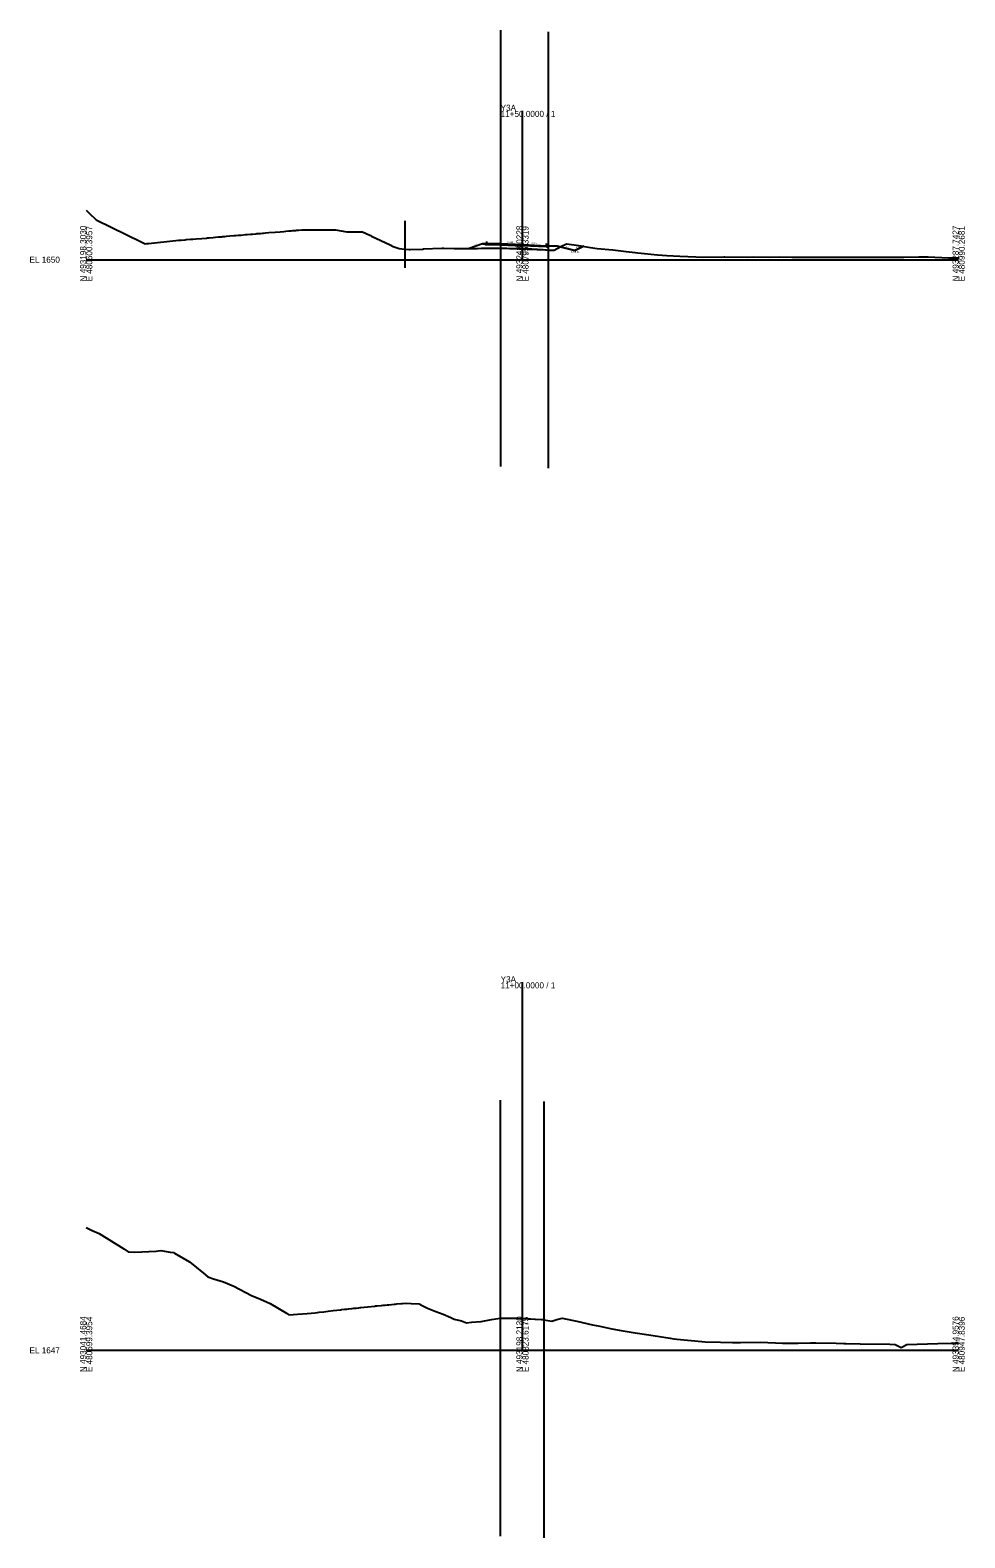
# Model space of a CAD drawing. Extents: x -26 to 403, y -10 to 3108.
# Drawn here: x -26 to 403, y 914 to 1605 of the extents above; entities that cross this region are included whole.
import ezdxf

# ---------------------------------------------------------------- set-up
doc = ezdxf.new("R2010")
doc.units = 0
for name, color, linetype in [('Exist Cross Section Cell', 7, 'Continuous'), ('Exist XS Center Line Elevation Label', 7, 'Continuous'), ('Exist XS Ground Line', 7, 'Continuous'), ('Prop Road Sect_ Boring - Header (ID Tx)', 7, 'Continuous'), ('Prop Road Sect_ Material - Tx (Composite Desc)', 7, 'Continuous'), ('Prop XS Ditch Slope Text', 7, 'Continuous'), ('Prop XS Ditch Standard Text', 7, 'Continuous'), ('Prop XS Dump Level', 7, 'Continuous'), ('Prop XS Earthwork Shape', 7, 'Continuous'), ('Prop XS EOT Tick Mark', 7, 'Continuous'), ('Prop XS Finish Grade', 7, 'Continuous'), ('Prop XS Finish Grade Earthwork', 7, 'Continuous'), ('Prop XS Finish Grade Pavement', 7, 'Continuous'), ('Prop XS Pvmt Edge Slope', 7, 'Continuous'), ('Prop XS SE Text', 7, 'Continuous'), ('Prop XS Side Slope Text', 7, 'Continuous'), ('Prop XS Subgrade Earthwork', 7, 'Continuous'), ('Scratch_Level_1', 7, 'Continuous'), ('Scratch_Level_4', 7, 'Continuous'), ('Scratch_Level_5', 7, 'Continuous')]:
    doc.layers.add(name, color=color, linetype=linetype)

msp = doc.modelspace()

# ---------------------------------------------------------------- linework, layer by layer
at = {"layer": 'Exist Cross Section Cell'}
for p, q in [((200, 1500), (200, 1568.23)), ((0, 1500), (200, 1500)), ((200, 1500), (400, 1500)), ((200, 1000), (200, 1168.72)), ((0, 1000), (200, 1000)), ((200, 1000), (400, 1000))]:
    msp.add_line(p, q, dxfattribs=at)
at = {"layer": 'Exist XS Ground Line'}
for points in [[(0, 1522.74), (1.43, 1521.37), (4.59, 1518.32), (25.48, 1508.09), (27.08, 1507.31), (27.82, 1507.39), (28.57, 1507.47), (41.07, 1508.82), (42.35, 1508.92), (42.82, 1508.95), (43.58, 1509.01), (45.32, 1509.14), (45.91, 1509.19), (47.89, 1509.34), (48.89, 1509.42), (50.47, 1509.55), (53.05, 1509.76), (55.14, 1509.92), (55.6, 1509.96), (56.34, 1510.03), (58.17, 1510.18), (59.3, 1510.28), (60.73, 1510.42), (62.04, 1510.54), (62.49, 1510.59), (62.86, 1510.62), (63.5, 1510.68), (64.28, 1510.75), (65.87, 1510.88), (67.65, 1511.02), (68.43, 1511.09), (69.74, 1511.2), (70.98, 1511.3), (73.03, 1511.48), (73.56, 1511.52), (73.87, 1511.55), (75.3, 1511.68), (76.24, 1511.76), (77.82, 1511.9), (78.17, 1511.93), (78.68, 1511.97), (79.48, 1512.04), (79.93, 1512.07), (80.87, 1512.15), (81.24, 1512.19), (82.21, 1512.27), (83.81, 1512.4), (86.59, 1512.62), (88.93, 1512.81), (90.58, 1512.94), (91.5, 1513.03), (92.95, 1513.16), (94.05, 1513.26), (94.72, 1513.32), (95.97, 1513.43), (96.47, 1513.47), (96.77, 1513.5), (97.5, 1513.55), (98.82, 1513.66), (99.51, 1513.71), (101.35, 1513.75), (109.82, 1513.74), (111.95, 1513.74), (113.14, 1513.75), (113.61, 1513.75), (114.25, 1513.61), (119.5, 1512.75), (124.95, 1512.8), (126.66, 1512.78), (129.97, 1511.28), (130.38, 1511.07), (130.84, 1510.78), (139.3, 1506.87), (140.69, 1506.04), (143.47, 1505.11), (144.72, 1504.92), (148, 1504.69), (148.53, 1504.71), (154.33, 1504.81), (154.7, 1504.94), (163.04, 1505.26), (164.02, 1505.24), (168.72, 1505.2), (170.95, 1505.18), (172.84, 1505.18), (173.59, 1505.18), (174.05, 1505.18), (176.14, 1505.18), (178.25, 1505.2), (178.72, 1505.2), (179.47, 1505.2), (181.28, 1505.21), (182.86, 1505.21), (183.86, 1505.22), (184.49, 1505.23), (186.42, 1505.23), (187.31, 1505.23), (188.67, 1505.22), (189.07, 1505.22), (189.88, 1505.23), (190.9, 1505.22), (191.58, 1505.22), (192.85, 1505.21), (194.13, 1505.19), (196.18, 1505.16), (196.7, 1505.15), (198.42, 1505.12), (199.47, 1505.11), (200, 1505.1), (201.18, 1505.08), (201.49, 1505.07), (201.81, 1505.06), (202.81, 1505.02), (204.35, 1504.95), (206.13, 1504.86), (206.92, 1504.82), (209.53, 1504.63), (210.6, 1504.53), (211.76, 1504.41), (214.54, 1504.32), (217.65, 1505.98), (220.2, 1507.2), (223.67, 1506.85), (231.14, 1505.61), (234.21, 1505.18), (241.4, 1504.46), (247.6, 1503.74), (251.66, 1503.25), (252.87, 1503.19), (261.92, 1502.26), (266.19, 1501.98), (272.19, 1501.61), (279.5, 1501.33), (282.45, 1501.21), (292.34, 1501.26), (292.82, 1501.26), (302.97, 1501.23), (306.14, 1501.27), (313.23, 1501.17), (317.68, 1501.29), (323.49, 1501.18), (326.03, 1501.21), (333.76, 1501.18), (337.07, 1501.16), (344.02, 1501.15), (346.09, 1501.18), (354.28, 1501.09), (359.4, 1501.13), (364.54, 1501.19), (367.76, 1501.12), (374.8, 1501.21), (381.8, 1501.26), (385.06, 1501.25), (386.04, 1501.25), (395.33, 1500.79), (399.35, 1500.86), (400, 1500.91)], [(0, 1056.24), (2.75, 1054.88), (5.99, 1053.49), (17.24, 1046.49), (19.22, 1045.22), (19.66, 1045.2), (22.2, 1045.07), (32.07, 1045.52), (34.28, 1045.7), (38.5, 1045.07), (40, 1044.83), (40.46, 1044.62), (47.44, 1040.54), (53.78, 1035.45), (55.83, 1033.77), (58.39, 1032.85), (62.95, 1031.39), (67.69, 1029.49), (75.79, 1025.16), (79.94, 1023.38), (84.31, 1021.45), (91.82, 1017.11), (92.95, 1016.23), (96.84, 1016.57), (101.34, 1016.94), (104.95, 1017.25), (106.02, 1017.37), (106.75, 1017.46), (109, 1017.72), (109.94, 1017.83), (110.87, 1017.94), (113.16, 1018.2), (114.89, 1018.4), (116.39, 1018.57), (116.71, 1018.6), (117.1, 1018.65), (118.47, 1018.8), (119.57, 1018.93), (120.25, 1019.01), (121.66, 1019.16), (122, 1019.2), (122.73, 1019.27), (123.75, 1019.38), (125.07, 1019.52), (125.56, 1019.57), (125.94, 1019.61), (127.37, 1019.76), (129.15, 1019.95), (132.3, 1020.29), (132.69, 1020.33), (133.01, 1020.36), (133.37, 1020.4), (135.44, 1020.59), (136.19, 1020.66), (137.14, 1020.76), (138.02, 1020.84), (138.73, 1020.9), (141.19, 1021.13), (141.81, 1021.19), (142.46, 1021.26), (144.54, 1021.46), (145.08, 1021.51), (146.28, 1021.58), (149.01, 1021.44), (152.59, 1021.37), (154.09, 1020.51), (156.52, 1019.29), (160.23, 1017.85), (163.71, 1016.57), (167.16, 1015.11), (168.64, 1014.26), (172.06, 1013.49), (174.43, 1012.64), (176.68, 1012.86), (181.11, 1013.27), (185.89, 1014.17), (189.75, 1014.73), (190.2, 1014.73), (190.95, 1014.73), (192.95, 1014.73), (193.54, 1014.72), (195.01, 1014.7), (196.12, 1014.69), (197.54, 1014.67), (199.25, 1014.64), (200.12, 1014.61), (201.56, 1014.55), (202.48, 1014.51), (203.84, 1014.44), (205.67, 1014.35), (206.02, 1014.32), (208.8, 1014.14), (209.17, 1014.11), (209.89, 1014.03), (212.63, 1013.46), (213.53, 1013.32), (215.77, 1014.07), (218.19, 1014.75), (224.96, 1013.31), (232.07, 1011.72), (233.82, 1011.44), (235.53, 1011.06), (240.94, 1009.93), (245.23, 1009.03), (251.63, 1008.01), (258, 1007.11), (267.74, 1005.57), (269.42, 1005.33), (270.76, 1005.17), (282.3, 1004.09), (283.84, 1003.96), (290.78, 1003.78), (296.28, 1003.54), (299.94, 1003.58), (309.04, 1003.74), (316.05, 1003.51), (319.26, 1003.31), (321.81, 1003.33), (326.38, 1003.34), (332.15, 1003.47), (334.57, 1003.45), (343.8, 1003.21), (347.33, 1003.12), (347.74, 1003.11), (348.25, 1003.11), (354.86, 1003.01), (368.5, 1002.8), (370.96, 1002.7), (371.84, 1002.26), (373.62, 1001.23), (376.24, 1002.62), (390.46, 1003.2), (396.56, 1003.24), (397.58, 1003.23), (398.38, 1003.25), (400, 1003.27)]]:
    msp.add_lwpolyline(points, dxfattribs=at)
at = {"layer": 'Prop Road Sect_ Boring - Header (ID Tx)'}
for points in [[(183.73, 1507.34), (182.67, 1507.3), (183.18, 1506.79)], [(211.02, 1506.41), (212.11, 1506.36), (211.59, 1505.84)]]:
    msp.add_lwpolyline(points, close=True, dxfattribs=at)
at = {"layer": 'Prop Road Sect_ Material - Tx (Composite Desc)'}
for points in [[(175.51, 1505.18), (176.14, 1505.18), (178.25, 1505.2), (178.72, 1505.2), (179.47, 1505.2), (181.28, 1505.21), (182.86, 1505.21), (183.86, 1505.22), (184.49, 1505.23), (186.42, 1505.23), (187.31, 1505.23), (188.67, 1505.22), (189.07, 1505.22), (189.88, 1505.23), (190.9, 1505.22), (191.58, 1505.22), (192.85, 1505.21), (194.13, 1505.19), (196.18, 1505.16), (196.7, 1505.15), (198.42, 1505.12), (199.47, 1505.11), (200, 1505.1), (201.18, 1505.08), (201.49, 1505.07), (201.81, 1505.06), (202.81, 1505.02), (204.35, 1504.95), (206.13, 1504.86), (206.92, 1504.82), (209.53, 1504.63), (210.6, 1504.53), (211.76, 1504.41), (214.54, 1504.32), (217.38, 1505.84), (216.02, 1506.18), (212.11, 1506.36), (211.59, 1505.84), (211.02, 1505.87), (199.98, 1506.37), (189.88, 1506.84), (183.73, 1506.8), (183.18, 1506.79), (182.67, 1507.3), (181.73, 1507.26)], [(217.38, 1505.84), (217.65, 1505.98), (220.2, 1507.2), (223.67, 1506.85), (227.95, 1506.14), (224.02, 1504.18)]]:
    msp.add_lwpolyline(points, close=True, dxfattribs=at)
at = {"layer": 'Prop XS Earthwork Shape'}
for points in [[(175.51, 1505.18), (176.14, 1505.18), (178.25, 1505.2), (178.72, 1505.2), (179.47, 1505.2), (181.28, 1505.21), (182.86, 1505.21), (183.86, 1505.22), (184.49, 1505.23), (186.42, 1505.23), (187.31, 1505.23), (188.67, 1505.22), (189.07, 1505.22), (189.88, 1505.23), (190.9, 1505.22), (191.58, 1505.22), (192.85, 1505.21), (194.13, 1505.19), (196.18, 1505.16), (196.7, 1505.15), (198.42, 1505.12), (199.47, 1505.11), (200, 1505.1), (201.18, 1505.08), (201.49, 1505.07), (201.81, 1505.06), (202.81, 1505.02), (204.35, 1504.95), (206.13, 1504.86), (206.92, 1504.82), (209.53, 1504.63), (210.6, 1504.53), (211.76, 1504.41), (214.54, 1504.32), (217.38, 1505.84), (216.02, 1506.18), (212.11, 1506.36), (211.59, 1505.84), (211.02, 1505.87), (199.98, 1506.37), (189.88, 1506.84), (183.73, 1506.8), (183.18, 1506.79), (182.67, 1507.3), (181.73, 1507.26)], [(217.38, 1505.84), (217.65, 1505.98), (220.2, 1507.2), (223.67, 1506.85), (227.95, 1506.14), (224.02, 1504.18)]]:
    msp.add_lwpolyline(points, close=True, dxfattribs=at)
at = {"layer": 'Prop XS EOT Tick Mark'}
for p, q in [((183.73, 1507.34), (183.73, 1508.34)), ((211.02, 1506.41), (211.02, 1507.41))]:
    msp.add_line(p, q, dxfattribs=at)
at = {"layer": 'Prop XS Finish Grade'}
for p, q in [((183.73, 1507.34), (182.67, 1507.3)), ((211.02, 1506.41), (212.11, 1506.36))]:
    msp.add_line(p, q, dxfattribs=at)
at = {"layer": 'Prop XS Finish Grade Earthwork'}
for p, q in [((181.73, 1507.26), (175.51, 1505.18)), ((181.73, 1507.26), (182.67, 1507.3)), ((212.11, 1506.36), (216.02, 1506.18)), ((216.02, 1506.18), (224.02, 1504.18)), ((224.02, 1504.18), (227.95, 1506.14))]:
    msp.add_line(p, q, dxfattribs=at)
at = {"layer": 'Prop XS Finish Grade Pavement'}
for p, q in [((189.88, 1507.38), (183.73, 1507.34)), ((189.88, 1507.38), (200, 1506.91)), ((200, 1506.91), (211.02, 1506.41))]:
    msp.add_line(p, q, dxfattribs=at)
at = {"layer": 'Prop XS Pvmt Edge Slope'}
for p, q in [((183.73, 1507.34), (183.18, 1506.79)), ((211.02, 1506.41), (211.59, 1505.84))]:
    msp.add_line(p, q, dxfattribs=at)
at = {"layer": 'Prop XS Subgrade Earthwork'}
for p, q in [((182.67, 1507.3), (183.18, 1506.79)), ((189.88, 1506.84), (183.73, 1506.8)), ((189.88, 1506.84), (199.98, 1506.37)), ((183.73, 1506.8), (183.18, 1506.79)), ((211.02, 1505.87), (199.98, 1506.37)), ((211.02, 1505.87), (211.59, 1505.84)), ((212.11, 1506.36), (211.59, 1505.84))]:
    msp.add_line(p, q, dxfattribs=at)
at = {"layer": 'Scratch_Level_1'}
for p, q in [((189.88, 1605.23), (189.88, 1405.23)), ((211.76, 1604.41), (211.76, 1404.41)), ((189.75, 1114.73), (189.75, 914.73)), ((209.89, 1114.03), (209.89, 914.03))]:
    msp.add_line(p, q, dxfattribs=at)
at = {"layer": 'Scratch_Level_4'}
msp.add_line((189.88, 1505.23), (211.02, 1504.48), dxfattribs=at)
at = {"layer": 'Scratch_Level_5'}
msp.add_line((146.1, 1517.82), (146.1, 1496.2), dxfattribs=at)

# ---------------------------------------------------------------- texts
at = {"layer": 'Exist Cross Section Cell'}
for s, p in [('Y3A', (190, 1568.23)), ('11+50.0000 / 1', (190, 1565.43)), ('EL 1650', (-26, 1498.6)), ('Y3A', (190, 1168.72)), ('11+00.0000 / 1', (190, 1165.92)), ('EL 1647', (-26, 998.6))]:
    msp.add_text(s, height=2.8, dxfattribs=at).set_placement(p)
for s, p in [('N 493198.3030', (0, 1490)), ('E 480600.3957', (2.8, 1490)), ('N 493243.0228', (200, 1490)), ('E 480795.3319', (202.8, 1490)), ('N 493287.7427', (400, 1490)), ('E 480990.2681', (402.8, 1490)), ('N 493041.4684', (0, 990)), ('E 480699.3954', (2.8, 990)), ('N 493198.2130', (200, 990)), ('E 480823.6175', (202.8, 990)), ('N 493354.9576', (400, 990)), ('E 480947.8396', (402.8, 990))]:
    msp.add_text(s, height=2.8, rotation=90, dxfattribs=at).set_placement(p)
at = {"layer": 'Exist XS Center Line Elevation Label'}
for s, p in [('1655.10', (198.07, 1502.2)), ('1661.62', (198.1, 1011.72))]:
    msp.add_text(s, height=0.9, dxfattribs=at).set_placement(p)
at = {"layer": 'Prop XS Ditch Slope Text'}
for s, rotation, p in [('3:1', 18.49244, (177.88, 1506.27)), ('4:1', 345.96376, (219.81, 1505.46))]:
    msp.add_text(s, height=0.75, rotation=rotation, dxfattribs=at).set_placement(p)
at = {"layer": 'Prop XS Ditch Standard Text'}
msp.add_text('1654.18', height=0.75, dxfattribs=at).set_placement((222.33, 1503.25))
at = {"layer": 'Prop XS Dump Level'}
for s, height, p in [('Case2', 0.04, (181.73, 1507.22)), ('Eop', 0.3, (189.88, 1504.93)), ('Eop', 0.3, (211.76, 1504.11)), ('Case2', 0.04, (216.02, 1506.14))]:
    msp.add_text(s, height=height, dxfattribs=at).set_placement(p)
at = {"layer": 'Prop XS SE Text'}
for p in [(193.17, 1507.73), (204.21, 1507.22)]:
    msp.add_text('0.046', height=0.75, rotation=357.36625, dxfattribs=at).set_placement(p)
at = {"layer": 'Prop XS Side Slope Text'}
msp.add_text('2:1', height=0.75, rotation=26.56505, dxfattribs=at).set_placement((224.79, 1504.92))

doc.saveas('drawing.dxf')
